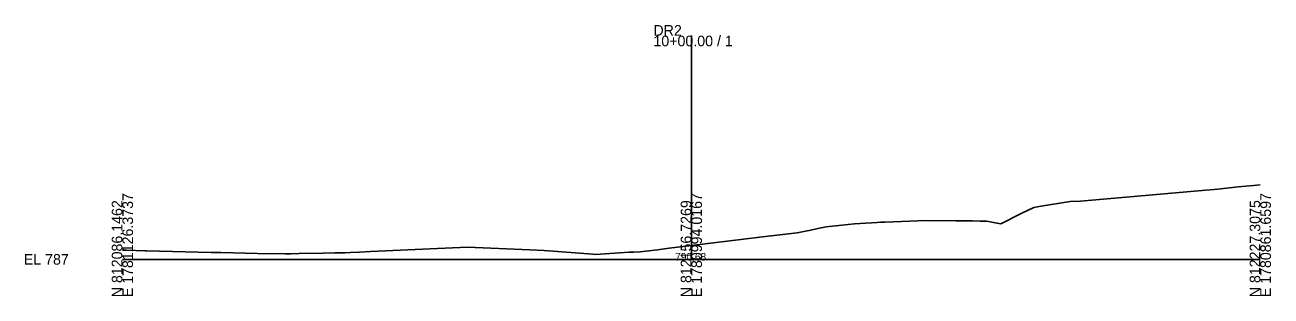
# Model space of a CAD drawing. Extents: x -26 to 303, y -10 to 2560.
# Drawn here: x -25.7 to 302.8, y -9.7 to 61.8 of the extents above; entities that cross this region are included whole.
import ezdxf

# ---------------------------------------------------------------- set-up
doc = ezdxf.new("R2010")
doc.units = 0
for name, color, linetype in [('Exist Cross Section Cell', 7, 'Continuous'), ('Exist XS Center Line Elevation Label', 7, 'Continuous'), ('Exist XS Ground Line', 7, 'Continuous')]:
    doc.layers.add(name, color=color, linetype=linetype)

msp = doc.modelspace()

# ---------------------------------------------------------------- linework, layer by layer
at = {"layer": 'Exist Cross Section Cell'}
for p, q in [((150, 0), (150, 59.01)), ((0, 0), (150, 0)), ((150, 0), (300, 0))]:
    msp.add_line(p, q, dxfattribs=at)
at = {"layer": 'Exist XS Ground Line'}
for p, q in [((252.62, 15.36), (285.68, 18.21)), ((285.68, 18.21), (287.84, 18.39)), ((287.84, 18.39), (288.81, 18.51)), ((288.81, 18.51), (294.19, 19.15)), ((294.19, 19.15), (298.24, 19.47)), ((298.24, 19.47), (300, 19.67)), ((237.17, 12.15), (240.31, 13.68)), ((240.31, 13.68), (242.26, 14.04)), ((242.26, 14.04), (249.89, 15.22)), ((249.89, 15.22), (252.62, 15.36)), ((201.05, 9.82), (211.88, 10.21)), ((211.88, 10.21), (219.74, 10.18)), ((219.74, 10.18), (224.08, 10.13)), ((224.08, 10.13), (226.11, 10.07)), ((226.11, 10.07), (227.94, 10.07)), ((227.94, 10.07), (230.08, 9.67)), ((231.57, 9.37), (237.17, 12.15)), ((168.8, 5.97), (177.89, 7.01)), ((177.89, 7.01), (180.08, 7.44)), ((180.08, 7.44), (181.47, 7.72)), ((181.47, 7.72), (183.37, 8.13)), ((183.37, 8.13), (185.55, 8.62)), ((185.55, 8.62), (189.66, 9.01)), ((189.66, 9.01), (193.02, 9.36)), ((193.02, 9.36), (198.98, 9.73)), ((198.98, 9.73), (199.89, 9.78)), ((199.89, 9.78), (201.05, 9.82)), ((230.08, 9.67), (231.57, 9.37)), ((144.11, 2.99), (150, 3.68)), ((150, 3.68), (163.06, 5.2)), ((163.06, 5.2), (168.8, 5.97)), ((0, 2.38), (1.03, 2.38)), ((1.03, 2.38), (6.01, 2.26)), ((6.01, 2.26), (6.38, 2.25)), ((6.38, 2.25), (23.41, 1.78)), ((23.41, 1.78), (25.94, 1.78)), ((25.94, 1.78), (35.62, 1.55)), ((35.62, 1.55), (43.04, 1.47)), ((43.04, 1.47), (44.28, 1.47)), ((44.28, 1.47), (46.65, 1.55)), ((46.65, 1.55), (52.92, 1.66)), ((52.92, 1.66), (55.99, 1.71)), ((55.99, 1.71), (58.75, 1.7)), ((58.75, 1.7), (60.1, 1.81)), ((60.1, 1.81), (62.48, 1.92)), ((62.48, 1.92), (65.44, 2.07)), ((65.44, 2.07), (90.96, 3.21)), ((90.96, 3.21), (107.4, 2.52)), ((107.4, 2.52), (111.21, 2.3)), ((111.21, 2.3), (124.01, 1.36)), ((124.01, 1.36), (124.76, 1.31)), ((124.76, 1.31), (133.61, 1.92)), ((133.61, 1.92), (134.85, 1.92)), ((134.85, 1.92), (136.52, 2)), ((136.52, 2), (141.04, 2.48)), ((141.04, 2.48), (144.11, 2.99))]:
    msp.add_line(p, q, dxfattribs=at)

# ---------------------------------------------------------------- texts
at = {"layer": 'Exist Cross Section Cell'}
for s, p in [('10+00.00 / 1', (140, 56.21)), ('DR2', (140, 59.01)), ('EL 787', (-26, -1.4))]:
    msp.add_text(s, height=2.8, dxfattribs=at).set_placement(p)
for s, p in [('E 1781126.3737', (2.8, -10)), ('E 1780994.0167', (152.8, -10)), ('E 1780861.6597', (302.8, -10)), ('N 812086.1462', (0, -10)), ('N 812156.7269', (150, -10)), ('N 812227.3075', (300, -10))]:
    msp.add_text(s, height=2.8, rotation=90, dxfattribs=at).set_placement(p)
at = {"layer": 'Exist XS Center Line Elevation Label'}
msp.add_text('790.68', height=2, dxfattribs=at).set_placement((145.73, -0.32))

doc.saveas('drawing.dxf')
